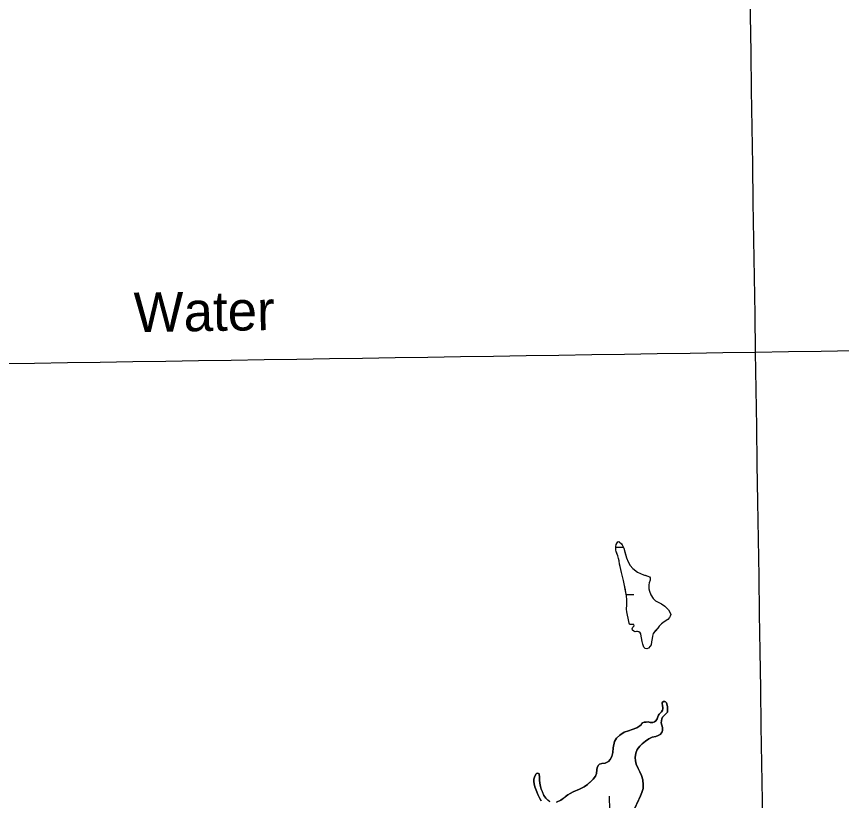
# Model space of a CAD drawing. Extents: x 3823584 to 3861785, y 301729 to 327625.
# Drawn here: x 3836481 to 3838570, y 312242 to 314225 of the extents above; entities that cross this region are included whole.
import ezdxf

# ---------------------------------------------------------------- set-up
doc = ezdxf.new("R2010")
doc.units = 0
for name, color, linetype in [('V-GRID-MAJR', 7, 'Continuous'), ('V-RIVR-IDEN', 7, 'Continuous'), ('V-TOPO-SHOR', 7, 'Continuous'), ('V-WETL-SWMP', 7, 'Continuous')]:
    doc.layers.add(name, color=color, linetype=linetype)

msp = doc.modelspace()

# ---------------------------------------------------------------- linework, layer by layer
at = {"layer": 'V-GRID-MAJR'}
for points in [[(3838444.8910000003, 307319.343), (3838352.38, 313376.366), (3838259.823, 319436.473), (3838167.2660000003, 325496.576), (3838167.219, 325499.664)], [(3827733.773, 313215.73), (3833043.082, 313295.662), (3838352.38, 313376.366), (3843661.667, 313457.842), (3848970.941, 313540.09), (3854280.204, 313623.11100000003), (3859589.454, 313706.903), (3859589.455, 313706.903)]]:
    msp.add_spline(points, degree=3, dxfattribs=at)
at = {"layer": 'V-TOPO-SHOR'}
for points in [[(3838031.259, 312694.801), (3838026.344, 312718.716), (3838025.832, 312725.994), (3838026.62, 312736.39), (3838026.627, 312743.406), (3838026.373, 312749.643), (3838025.343, 312759.52), (3838024.312, 312767.579), (3838022.7600000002, 312774.597), (3838021.208, 312782.134), (3838019.6550000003, 312789.673), (3838017.843, 312797.992), (3838012.665, 312818.527), (3838010.855, 312826.328), (3838009.561, 312833.604), (3838008.2660000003, 312839.585), (3838006.716, 312848.162), (3838005.424, 312854.402), (3838003.869, 312860.898), (3838001.537, 312866.618), (3837999.4620000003, 312871.56), (3837998.946, 312875.197), (3837998.43, 312879.617), (3837998.436, 312884.555), (3837999.738, 312889.752), (3838001.561, 312893.908), (3838003.384, 312896.505), (3838003.644, 312896.505), (3838006.2430000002, 312896.76300000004), (3838007.281, 312895.982), (3838012.735, 312890.778), (3838014.552, 312888.177), (3838018.443, 312879.858), (3838021.552, 312869.979), (3838025.957, 312855.68), (3838029.844, 312845.54), (3838035.034, 312836.181), (3838041.524, 312828.636), (3838053.47, 312819.789), (3838061.002, 312816.143), (3838068.2770000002, 312813.018), (3838072.694, 312811.453), (3838079.1890000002, 312809.108), (3838083.6040000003, 312807.286), (3838085.163, 312805.205), (3838085.421, 312803.384), (3838085.416, 312798.967), (3838083.072, 312792.47000000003), (3838081.767, 312787.014), (3838081.759, 312777.659), (3838083.571, 312771.42100000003), (3838087.46, 312762.32), (3838092.9080000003, 312752.69800000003), (3838098.622, 312746.974), (3838105.3740000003, 312743.331), (3838114.467, 312738.903), (3838122.518, 312733.179), (3838128.49, 312727.454), (3838131.865, 312723.813), (3838136.795, 312715.23), (3838137.573, 312712.373), (3838136.528, 312707.955), (3838134.446, 312704.318), (3838130.024, 312699.645)], [(3838038.528, 312686.738), (3838034.845, 312686.824), (3838033.307, 312687.55700000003), (3838032.238, 312690.36100000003), (3838031.259, 312694.801)], [(3838130.024, 312699.645), (3838123.782, 312695.231), (3838117.279, 312691.34), (3838113.898, 312688.483), (3838108.694, 312682.771), (3838104.793, 312677.578), (3838098.548, 312670.567), (3838093.344, 312664.593), (3838091.52, 312657.839), (3838090.213, 312651.863), (3838089.164, 312643.028), (3838087.86, 312635.491), (3838085.517, 312631.856), (3838081.353, 312627.18), (3838077.194, 312625.626), (3838072.776, 312626.668), (3838069.659, 312629.531), (3838067.068, 312637.07), (3838065.256, 312644.349), (3838063.966, 312653.188), (3838062.929, 312657.866), (3838061.6350000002, 312663.586), (3838060.339, 312665.664), (3838056.704, 312668.527), (3838053.845, 312669.57), (3838050.986, 312669.314), (3838047.606, 312668.79600000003), (3838043.969, 312669.838), (3838040.852, 312672.441), (3838039.558, 312676.08), (3838041.38, 312680.498), (3838043.461, 312682.315), (3838044.762, 312683.613), (3838044.506, 312686.732), (3838041.907, 312686.994), (3838038.528, 312686.738)], [(3838044.588, 312219.32300000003), (3838057.504, 312245.609), (3838061.379, 312253.598), (3838064.48, 312261.588), (3838067.585, 312271.897), (3838068.109, 312281.693), (3838066.575, 312293.813), (3838063.491, 312304.901), (3838059.116, 312314.445), (3838055.258, 312322.442), (3838050.369, 312333.27400000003), (3838048.057, 312342.041), (3838047.551, 312350.551), (3838049.1070000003, 312361.377), (3838052.9820000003, 312370.654), (3838059.18, 312378.89900000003), (3838065.373, 312385.08), (3838073.37, 312391.775), (3838082.4, 312397.69800000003), (3838090.653, 312401.556), (3838099.423, 312403.868), (3838105.87, 312405.925), (3838110.771, 312409.01300000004), (3838115.1580000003, 312413.39400000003), (3838116.968, 312419.063), (3838116.46, 312426.54), (3838115.176, 312431.957), (3838113.378, 312437.88800000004), (3838113.898, 312443.301), (3838114.934, 312448.197), (3838117.001, 312452.578), (3838129.129, 312465.458), (3838129.401, 312479.63800000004), (3838127.089, 312488.664), (3838123.9990000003, 312491.76), (3838122.711, 312492.53500000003), (3838118.586, 312491.767), (3838117.554, 312491.25), (3838116.005, 312489.19), (3838116.511, 312480.683), (3838117.539, 312477.586), (3838117.793, 312473.462), (3838117.017, 312470.11100000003), (3838114.435, 312465.988), (3838110.824, 312462.64), (3838107.983, 312460.066), (3838106.951, 312457.745), (3838104.627, 312453.106), (3838103.074, 312448.468), (3838099.9760000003, 312443.315), (3838096.879, 312440.481), (3838091.978, 312438.938), (3838085.791, 312439.461), (3838080.12, 312440.49700000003), (3838075.222, 312440.245), (3838070.323, 312439.47500000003), (3838065.94, 312438.191), (3838065.682, 312437.675), (3838063.8740000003, 312434.582), (3838062.5810000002, 312432.78), (3838059.745, 312430.204), (3838051.489, 312425.313), (3838039.883, 312421.715), (3838030.342, 312418.37200000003), (3838019.768, 312414.25800000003), (3838008.674, 312406.793), (3838000.674, 312399.582), (3837994.9930000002, 312390.563), (3837991.884, 312375.354), (3837990.842, 312363.496), (3837988.253, 312352.67), (3837984.639, 312345.711), (3837979.734, 312340.045)], [(3837979.734, 312340.045), (3837971.222, 312336.444), (3837962.971, 312335.162), (3837957.556, 312333.364), (3837954.717, 312331.04600000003), (3837951.103, 312324.86100000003), (3837950.58, 312319.706), (3837950.056, 312310.424), (3837947.213, 312303.465), (3837941.276, 312295.994), (3837935.083, 312290.071), (3837926.826, 312282.344), (3837918.828, 312276.423), (3837906.9620000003, 312269.989), (3837890.971, 312263.56), (3837883.234, 312259.699), (3837877.301, 312256.09500000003), (3837870.592, 312251.202), (3837867.497, 312248.628), (3837863.108, 312245.021), (3837859.239, 312242.447), (3837848.406, 312237.303)], [(3837831.133, 312238.091), (3837826.754, 312242.222), (3837821.0870000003, 312247.641), (3837816.711, 312254.606), (3837813.6240000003, 312261.827), (3837809.7660000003, 312270.599), (3837807.71, 312276.788), (3837806.1720000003, 312285.553), (3837805.664, 312293.547), (3837805.412, 312299.994), (3837804.39, 312309.533), (3837802.844, 312310.308), (3837801.295, 312310.826), (3837797.9450000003, 312309.798), (3837796.397, 312308.509), (3837792.522, 312301.036), (3837791.227, 312295.882), (3837790.963, 312289.953), (3837791.989, 312283.76300000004), (3837793.785, 312276.026), (3837795.072, 312271.901), (3837798.674, 312263.646), (3837801.244, 312256.943), (3837806.133, 312246.367), (3837809.737, 312241.206)]]:
    msp.add_lwpolyline(points, dxfattribs=at)
at = {"layer": 'V-WETL-SWMP'}
for p, q in [((3837998.43289569, 312882.4767836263), (3838017.0827964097, 312882.7643412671)), ((3838024.9233376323, 312762.79996058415), (3838044.211683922, 312763.0973622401)), ((3837983.470517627, 312216.8172926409), (3837982.9155093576, 312252.81301343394))]:
    msp.add_line(p, q, dxfattribs=at)
msp.add_lwpolyline([(3838031.259, 312694.801), (3838026.344, 312718.716), (3838025.8310000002, 312725.994), (3838026.6210000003, 312736.389), (3838026.627, 312743.406), (3838026.373, 312749.643), (3838025.343, 312759.52), (3838024.312, 312767.578), (3838017.843, 312797.992), (3838012.665, 312818.528), (3838010.8540000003, 312826.327), (3838009.561, 312833.605), (3838008.267, 312839.58400000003), (3838006.716, 312848.162), (3838005.423, 312854.401), (3838003.87, 312860.89900000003), (3837999.4620000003, 312871.559), (3837998.9450000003, 312875.19800000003), (3837998.43, 312879.617), (3837998.435, 312884.555), (3837999.739, 312889.752), (3838001.562, 312893.908), (3838003.384, 312896.505), (3838006.2430000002, 312896.762), (3838007.282, 312895.982), (3838012.735, 312890.779), (3838014.551, 312888.178), (3838018.4420000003, 312879.858), (3838025.9560000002, 312855.68), (3838029.844, 312845.541), (3838035.0330000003, 312836.18), (3838041.523, 312828.636), (3838053.47, 312819.789), (3838061.003, 312816.143), (3838068.2770000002, 312813.017), (3838079.1890000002, 312809.108), (3838083.605, 312807.28500000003), (3838085.163, 312805.204), (3838085.421, 312803.385), (3838085.417, 312798.966), (3838083.071, 312792.471), (3838081.767, 312787.015), (3838081.758, 312777.659), (3838083.571, 312771.42), (3838087.461, 312762.32), (3838092.909, 312752.69800000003), (3838098.6210000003, 312746.97500000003), (3838105.375, 312743.33), (3838114.467, 312738.903), (3838122.518, 312733.178), (3838128.49, 312727.454), (3838131.865, 312723.813), (3838136.795, 312715.231), (3838137.572, 312712.37200000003), (3838136.528, 312707.955), (3838134.446, 312704.318), (3838130.023, 312699.64400000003), (3838123.781, 312695.232), (3838117.2800000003, 312691.34), (3838113.899, 312688.484), (3838108.6950000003, 312682.772), (3838104.792, 312677.578), (3838093.344, 312664.594), (3838091.519, 312657.838), (3838090.213, 312651.862), (3838089.165, 312643.027), (3838087.859, 312635.491), (3838085.5160000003, 312631.855), (3838081.353, 312627.181), (3838077.193, 312625.625), (3838072.776, 312626.669), (3838069.66, 312629.531), (3838067.069, 312637.07), (3838065.256, 312644.349), (3838063.965, 312653.18700000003), (3838061.636, 312663.585), (3838060.339, 312665.665), (3838056.703, 312668.528), (3838053.845, 312669.57), (3838050.986, 312669.313), (3838047.6070000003, 312668.79600000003), (3838043.97, 312669.839), (3838040.853, 312672.441), (3838039.557, 312676.081), (3838041.381, 312680.49700000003), (3838043.4620000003, 312682.315), (3838044.762, 312683.613), (3838044.506, 312686.732), (3838041.907, 312686.994), (3838038.528, 312686.738), (3838034.846, 312686.825), (3838033.308, 312687.558), (3838032.239, 312690.36100000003)], close=True, dxfattribs=at)
for points in [[(3837848.406, 312237.302), (3837859.239, 312242.44800000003), (3837863.109, 312245.022), (3837870.592, 312251.203), (3837877.3000000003, 312256.09500000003), (3837883.233, 312259.699), (3837890.971, 312263.559), (3837906.9620000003, 312269.989), (3837918.828, 312276.423), (3837926.826, 312282.34500000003), (3837941.2770000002, 312295.995), (3837947.214, 312303.466), (3837950.056, 312310.425), (3837950.5810000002, 312319.705), (3837951.102, 312324.86100000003), (3837954.717, 312331.045), (3837957.555, 312333.363), (3837962.971, 312335.163), (3837971.222, 312336.444), (3837979.734, 312340.045), (3837984.6380000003, 312345.712), (3837988.254, 312352.67), (3837990.842, 312363.496), (3837991.8850000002, 312375.354), (3837994.994, 312390.56200000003), (3838000.674, 312399.581), (3838008.673, 312406.792), (3838019.767, 312414.25800000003), (3838030.341, 312418.373), (3838039.884, 312421.715), (3838051.489, 312425.314), (3838059.744, 312430.204), (3838062.582, 312432.78), (3838063.873, 312434.583), (3838065.9390000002, 312438.191), (3838070.323, 312439.47500000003), (3838075.222, 312440.244), (3838080.1210000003, 312440.49700000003), (3838085.792, 312439.461), (3838091.9790000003, 312438.939), (3838096.879, 312440.481), (3838099.9760000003, 312443.314), (3838103.075, 312448.468), (3838104.626, 312453.107), (3838106.951, 312457.745), (3838107.984, 312460.065), (3838114.435, 312465.988), (3838117.017, 312470.11100000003), (3838117.794, 312473.462), (3838117.54, 312477.587), (3838116.512, 312480.68200000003), (3838116.005, 312489.19), (3838117.5530000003, 312491.251), (3838118.585, 312491.766)], [(3838118.585, 312491.766), (3838122.711, 312492.53500000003), (3838123.9990000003, 312491.761), (3838127.09, 312488.664), (3838129.4020000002, 312479.63800000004), (3838129.13, 312465.458), (3838117.001, 312452.579), (3838114.934, 312448.19800000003), (3838113.898, 312443.301), (3838113.377, 312437.887), (3838115.176, 312431.956), (3838116.46, 312426.54), (3838116.968, 312419.063), (3838115.1580000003, 312413.393), (3838110.771, 312409.014), (3838105.87, 312405.925), (3838099.4220000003, 312403.869), (3838090.654, 312401.55700000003), (3838082.4, 312397.697), (3838073.3710000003, 312391.776), (3838065.372, 312385.081), (3838059.179, 312378.89900000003), (3838052.983, 312370.655), (3838049.1070000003, 312361.377), (3838047.5500000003, 312350.55), (3838048.057, 312342.042), (3838050.369, 312333.27400000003), (3838055.257, 312322.441), (3838059.117, 312314.445), (3838063.491, 312304.901), (3838066.574, 312293.81200000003), (3838068.109, 312281.693), (3838067.5840000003, 312271.897), (3838064.48, 312261.587), (3838061.379, 312253.598), (3838044.588, 312219.324)], [(3837809.737, 312241.207), (3837806.133, 312246.366), (3837801.244, 312256.942), (3837798.673, 312263.647), (3837795.071, 312271.901), (3837793.786, 312276.027), (3837791.989, 312283.76300000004), (3837790.964, 312289.952), (3837791.227, 312295.882), (3837792.521, 312301.037), (3837796.396, 312308.51), (3837797.944, 312309.797), (3837801.296, 312310.825), (3837802.843, 312310.308), (3837804.389, 312309.533), (3837805.411, 312299.993), (3837805.663, 312293.547), (3837806.171, 312285.554), (3837807.7090000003, 312276.787), (3837809.7660000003, 312270.598), (3837816.711, 312254.606), (3837821.0870000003, 312247.641), (3837831.133, 312238.092)]]:
    msp.add_lwpolyline(points, dxfattribs=at)

# ---------------------------------------------------------------- texts
at = {"layer": 'V-RIVR-IDEN'}
msp.add_text('Water', height=99.99980199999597, rotation=0.8425138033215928, dxfattribs=at).set_placement((3836778.890402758, 313426.90012083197))

doc.saveas('drawing.dxf')
